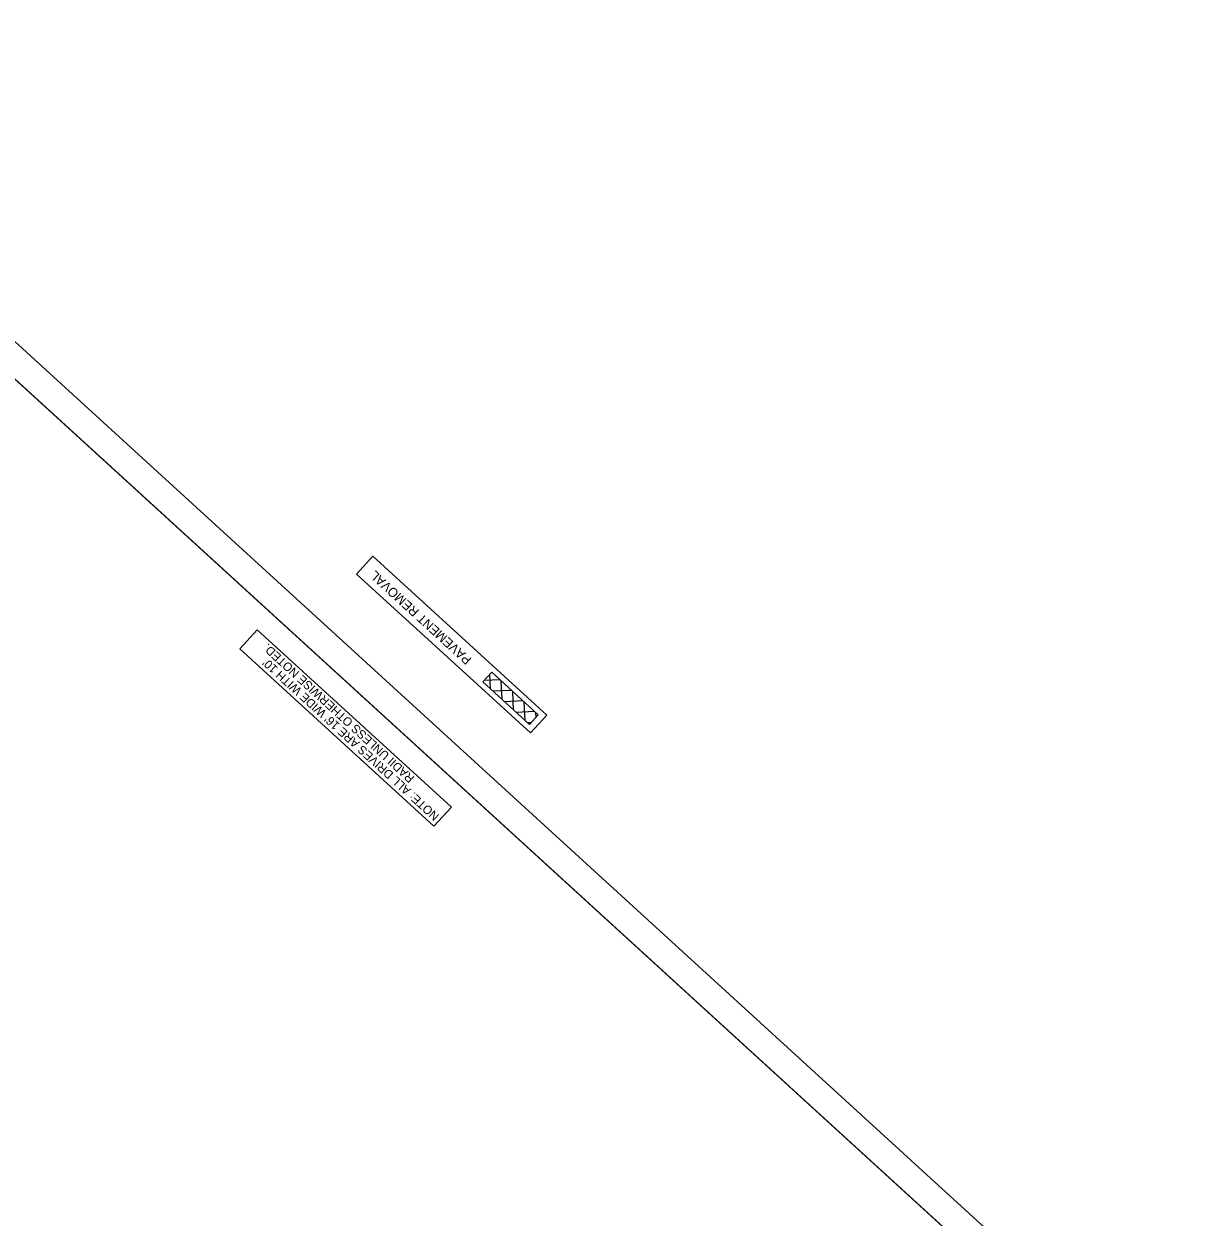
# Model space of a CAD drawing. Extents: x 475722 to 477703, y 499689 to 501633.
# Drawn here: x 476751 to 477703, y 500661 to 501633 of the extents above; entities that cross this region are included whole.
import ezdxf

# ---------------------------------------------------------------- set-up
doc = ezdxf.new("R2010")
doc.units = 0
for name, color, linetype in [('Prop DSN Text', 7, 'Continuous'), ('Prop Grid Mask', 7, 'Continuous'), ('Prop Rem of Exist Asph Pvmt', 7, 'Continuous'), ('Sheet Clip Boundary CELL', 7, 'Continuous'), ('Sheet Plan CELL', 7, 'Continuous'), ('Sheet Plot Border Outside CELL', 7, 'Continuous')]:
    doc.layers.add(name, color=color, linetype=linetype)

msp = doc.modelspace()

# ---------------------------------------------------------------- linework, layer by layer
at = {"layer": 'Prop DSN Text'}
msp.add_lwpolyline([(477124.71, 501097.44), (477162.71, 501062.72), (477169.83, 501070.51), (477131.84, 501105.24)], close=True, dxfattribs=at)
at = {"layer": 'Prop Grid Mask'}
for points in [[(477176.75, 501070.32), (477035.13, 501199.73), (477021.9, 501185.26), (477163.53, 501055.85)], [(477084.86, 500979.8), (476926.68, 501124.35), (476940.84, 501139.84), (477099.03, 500995.3)]]:
    msp.add_lwpolyline(points, close=True, dxfattribs=at)
at = {"layer": 'Prop Rem of Exist Asph Pvmt'}
for p, q in [((477138.63, 501099.03), (477125.63, 501098.44)), ((477130.91, 501091.78), (477130.37, 501103.63)), ((477140.3, 501083.2), (477139.63, 501098.11)), ((477148.03, 501090.44), (477133.11, 501089.77)), ((477149.7, 501074.61), (477149.03, 501089.53)), ((477157.42, 501081.85), (477142.51, 501081.18)), ((477159.1, 501066.02), (477158.42, 501080.94)), ((477166.82, 501073.27), (477151.9, 501072.6)), ((477167.99, 501068.5), (477167.82, 501072.35)), ((477164, 501064.13), (477161.3, 501064.01))]:
    msp.add_line(p, q, dxfattribs=at)
at = {"layer": 'Sheet Clip Boundary CELL'}
msp.add_lwpolyline([(475896.94, 500695.24), (476776.38, 499891.66), (476856.61, 499818.34), (476969.21, 499941.58), (477026.31, 500152.38), (477503.19, 500649.86), (476731.13, 501355.34), (476672.99, 501291.71), (476544.91, 501408.73), (475869.73, 500955.21), (476014.01, 500823.37)], close=True, dxfattribs=at)
at = {"layer": 'Sheet Plan CELL'}
msp.add_lwpolyline([(475749.25, 500830.21), (476856.61, 499818.34), (477564.89, 500593.48), (476457.56, 501605.32)], close=True, dxfattribs=at)
at = {"layer": 'Sheet Plot Border Outside CELL'}
msp.add_lwpolyline([(477702.99, 500497.79), (476460.19, 501633.41), (475721.55, 500825.06), (476964.34, 499689.44)], close=True, dxfattribs=at)

# ---------------------------------------------------------------- texts
at = {"layer": 'Prop DSN Text'}
for s, height, rotation, p in [('PAVEMENT REMOVAL', 7.5, 137.57997, (477116.12, 501116.33)), ('   RADII UNLESS OTHERWISE NOTED. ', 7, 137.57996, (477075.21, 501014.43)), ("NOTE: ALL DRIVES ARE 16' WIDE WITH 10'", 7, 137.57996, (477089.69, 500988.77))]:
    msp.add_text(s, height=height, rotation=rotation, dxfattribs=at).set_placement(p)

doc.saveas('drawing.dxf')
